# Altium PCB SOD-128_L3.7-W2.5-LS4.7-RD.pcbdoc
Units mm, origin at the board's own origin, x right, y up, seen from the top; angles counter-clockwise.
Board outline 18.35 x 15.45 mm, 2 copper layers (Top Layer, Bottom Layer), stack 0 mm thick; 1 components, 0 nets, 2 pads, 0 vias.
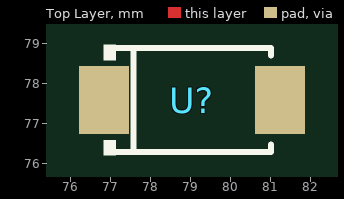
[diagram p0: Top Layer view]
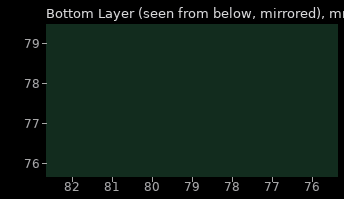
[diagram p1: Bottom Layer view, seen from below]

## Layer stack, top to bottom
Top Layer: signal copper (thickness not stored)
Bottom Layer: signal copper (thickness not stored)

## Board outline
88.2,69.85 69.85,69.85 69.85,85.305 88.2,85.305

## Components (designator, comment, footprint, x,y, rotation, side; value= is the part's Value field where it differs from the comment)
U? "" SOD-128_L3.7-W2.5-LS4.7-RD 79.025,77.577 r0 top

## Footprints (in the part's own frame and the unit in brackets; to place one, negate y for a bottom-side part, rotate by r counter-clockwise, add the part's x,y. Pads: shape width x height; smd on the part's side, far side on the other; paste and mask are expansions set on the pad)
SOD-128_L3.7-W2.5-LS4.7-RD [mm]
  rect 1.25x1.7 smd: 1(-2.2,0) 2(2.2,0)
  silkscreen extent -2.2,-1.38 1.98,1.38

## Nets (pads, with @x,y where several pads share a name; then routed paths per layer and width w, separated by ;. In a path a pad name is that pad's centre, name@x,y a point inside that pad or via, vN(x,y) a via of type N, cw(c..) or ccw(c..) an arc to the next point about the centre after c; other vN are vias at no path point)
pads on no net: U?.1 U?.2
